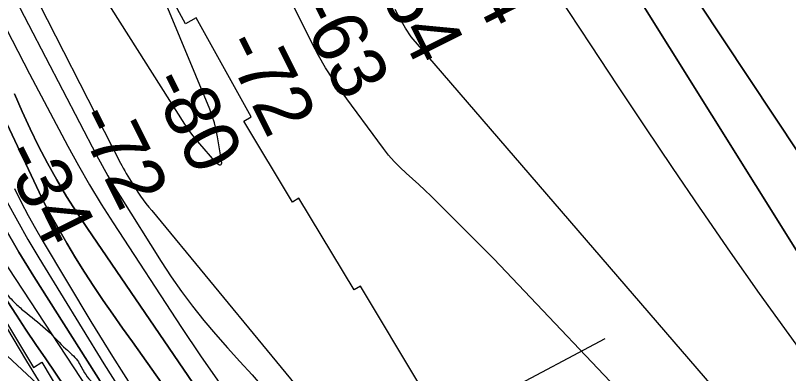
# Model space of a CAD drawing. Extents: x 3297753 to 3335611, y 652252 to 677623.
# Drawn here: x 3308869 to 3309808, y 671345 to 671780 of the extents above; entities that cross this region are included whole.
import ezdxf

# ---------------------------------------------------------------- set-up
doc = ezdxf.new("R2010")
doc.units = 0
for name, color, linetype in [('V-RIVR-EDGE', 7, 'Continuous'), ('V-RIVR-RANG', 7, 'Continuous'), ('V-RRAP-FSHR', 7, 'Continuous'), ('V-RRAP-RVMT', 7, 'Continuous'), ('V-TOPO-DPTH', 7, 'Continuous'), ('V-TOPO-MAJR', 7, 'Continuous'), ('V-TOPO-MINR', 7, 'Continuous'), ('V-TOPO-WATR', 7, 'Continuous')]:
    doc.layers.add(name, color=color, linetype=linetype)

msp = doc.modelspace()

# ---------------------------------------------------------------- linework, layer by layer
at = {"layer": 'V-RIVR-EDGE'}
msp.add_spline([(3307850.62, 675821), (3307850.75, 675819.26), (3307852.36, 675798.53), (3307852.34, 675791.07), (3307856.9, 675791.47), (3307860.2, 675784), (3307858.08, 675766.6), (3307858.03, 675745.87), (3307859.68, 675743.8), (3307863.41, 675742.96), (3307863.4, 675739.64), (3307862.94, 675720.99), (3307866.19, 675694.04), (3307864.47, 675668.35), (3307864.85, 675653.43), (3307866.04, 675632.29), (3307865.98, 675608.25), (3307860.93, 675578), (3307855.03, 675536.15), (3307852.01, 675490.98), (3307848.61, 675457.42), (3307845.62, 675420.95), (3307843.09, 675401.89), (3307841.81, 675387.8), (3307842.17, 675364.59), (3307841.69, 675337.23), (3307844.13, 675320.65), (3307845.74, 675299.92), (3307848.96, 675263.02), (3307851.37, 675230.27), (3307851.72, 675204.99), (3307854.14, 675179.28), (3307856.98, 675153.99), (3307856.53, 675138.24), (3307855.69, 675135.76), (3307856.07, 675118.35), (3307855.63, 675111.72), (3307854.35, 675095.97), (3307852.65, 675077.74), (3307852.18, 675054.11), (3307855.44, 675031.72), (3307862.38, 674991.5), (3307864.8, 674962.48), (3307868.44, 674926), (3307870.05, 674906.1), (3307872.46, 674875.01), (3307874.08, 674859.25), (3307876.52, 674843.5), (3307878.94, 674816.13), (3307882.53, 674757.68), (3307886.15, 674712.5), (3307885.71, 674704.21), (3307884.45, 674697.99), (3307884.44, 674691.78), (3307887.31, 674680.16), (3307887.28, 674668.97), (3307887.26, 674658.2), (3307885.58, 674651.15), (3307881.01, 674644.12), (3307881, 674639.97), (3307886.35, 674626.28), (3307890.03, 674605.55), (3307895.77, 674578.59), (3307899.43, 674550.81), (3307909.27, 674510.58), (3307914.59, 674481.97), (3307918.25, 674453.78), (3307918.22, 674440.51), (3307919.86, 674433.88), (3307927.3, 674423.08), (3307927.28, 674417.7), (3307927.25, 674404.02), (3307928.48, 674400.28), (3307931.78, 674393.23), (3307935.06, 674376.64), (3307944.54, 674357.55), (3307954.85, 674337.22), (3307963.92, 674316.06), (3307975.42, 674271.68), (3307986.49, 674225.23), (3308000.06, 674178.77), (3308007.44, 674148.91), (3308015.22, 674108.27), (3308020.53, 674078.42), (3308024.25, 674072.19), (3308025.04, 674059.34), (3308025.41, 674039.44), (3308027.79, 673997.16), (3308030.63, 673971.46), (3308027.69, 673955.3), (3308027.24, 673943.28), (3308027.64, 673935.82), (3308029.69, 673925.45), (3308035.46, 673911.76), (3308035.42, 673899.32), (3308034.12, 673873.21), (3308036.13, 673851.24), (3308038.54, 673818.91), (3308040.98, 673799), (3308046.76, 673788.21), (3308050.46, 673778.26), (3308048.79, 673772.46), (3308048.76, 673761.27), (3308053.68, 673740.53), (3308060.66, 673711.09), (3308069.7, 673678.73), (3308069.66, 673665.06), (3308067.15, 673653.46), (3308067.55, 673650.14), (3308072.94, 673649.3), (3308077.91, 673648.87), (3308079.98, 673646.38), (3308086.52, 673608.64), (3308091.84, 673582.1), (3308104.58, 673536.48), (3308114.83, 673495), (3308121.38, 673461), (3308123.83, 673446.07), (3308127.95, 673436.12), (3308140.31, 673406.24), (3308148.95, 673377.21), (3308153.04, 673357.72), (3308158.34, 673321.23), (3308169, 673273.12), (3308189.1, 673188.1), (3308196.88, 673150.37), (3308207.96, 673103.92), (3308212.04, 673079.45), (3308214.06, 673059.97), (3308216.51, 673045.04), (3308218.98, 673035.91), (3308226, 673025.53), (3308228.46, 673015.99), (3308228.43, 673002.32), (3308230.49, 672996.92), (3308235.04, 672992.77), (3308235.02, 672984.48), (3308237.47, 672972.87), (3308241.99, 672953.37), (3308247.32, 672933.05), (3308253.9, 672910.65), (3308257.61, 672901.53), (3308263.8, 672890.32), (3308276.17, 672865), (3308277.39, 672856.3), (3308278.62, 672850.08), (3308283.16, 672844.26), (3308286.05, 672839.7), (3308286.04, 672832.24), (3308285.59, 672818.97), (3308288.47, 672812.33), (3308293.83, 672800.3), (3308303.72, 672777.89), (3308309.9, 672762.54), (3308316.07, 672743.05), (3308316.44, 672725.64), (3308318.1, 672723.15), (3308323.06, 672717.33), (3308327.59, 672706.13), (3308331.69, 672690.37), (3308330.84, 672679.6), (3308330.4, 672672.14), (3308332.46, 672667.16), (3308337.42, 672658.44), (3308343.59, 672642.67), (3308347.7, 672625.26), (3308355.91, 672595.39), (3308355.89, 672584.62), (3308357.53, 672579.64), (3308362.07, 672570.92), (3308366.61, 672563.45), (3308376.07, 672534), (3308399.56, 672478.4), (3308411.51, 672452.67), (3308418.52, 672435.25), (3308421.79, 672418.66), (3308423.01, 672409.95), (3308425.49, 672403.73), (3308428.79, 672397.5), (3308430.01, 672387.55), (3308434.95, 672375.52), (3308444.41, 672344.83), (3308450.58, 672326.99), (3308456.78, 672320.76), (3308459.66, 672312.87), (3308465.4, 672287.99), (3308467.43, 672268.09), (3308473.18, 672249.01), (3308476.05, 672236.57), (3308485.95, 672214.16), (3308490.05, 672198.81), (3308495.86, 672201.7), (3308496.67, 672193), (3308499.08, 672161.9), (3308505.23, 672134.53), (3308513.87, 672107.57), (3308522.52, 672084.75), (3308527.9, 672082.25), (3308536.2, 672087.2), (3308540.76, 672086.78), (3308539.51, 672083.88), (3308535.76, 672077.67), (3308534.91, 672067.73), (3308534.47, 672059.44), (3308531.96, 672050.74), (3308533.2, 672047.42), (3308536.91, 672037.88), (3308550.93, 672008.42), (3308564.93, 671974.39), (3308569.87, 671959.46), (3308576.49, 671954.88), (3308585.14, 671932.48), (3308595.86, 671910.49), (3308604.94, 671895.13), (3308605.76, 671888.49), (3308607.82, 671885.17), (3308610.71, 671881.02), (3308616.47, 671862.77), (3308627.6, 671838.7), (3308640.39, 671816.29), (3308660.99, 671765.26), (3308672.95, 671740.77), (3308685.32, 671715.46), (3308698.53, 671692.21), (3308700.17, 671685.58), (3308711.29, 671658.19), (3308728.21, 671627.9), (3308743.07, 671602.99), (3308758.34, 671575.6), (3308771.97, 671554.84), (3308775.27, 671548.61), (3308783.11, 671536.16), (3308790.54, 671522.88), (3308793.43, 671519.55), (3308797.16, 671517.06), (3308801.29, 671511.24), (3308803.76, 671502.95), (3308810.8, 671502.1), (3308815.77, 671499.19), (3308833.53, 671474.28), (3308845.09, 671458.5), (3308857.08, 671443.55), (3308870.72, 671429.01), (3308882.71, 671418.61), (3308908.77, 671397), (3308930.27, 671375.39), (3308944.33, 671361.26), (3308952.58, 671346.74), (3308960.43, 671336.77), (3308966.22, 671331.78), (3308972.85, 671328.86), (3308985.64, 671307.28), (3309001.75, 671282.37), (3309010.84, 671271.57), (3309010.83, 671268.25), (3309008.34, 671266.19), (3309011.64, 671262.03), (3309018.66, 671250.83), (3309024.85, 671237.13), (3309035.15, 671212.24), (3309059.5, 671169.07), (3309066.5, 671150.82), (3309067.71, 671140.45), (3309071.85, 671135.88), (3309077.22, 671128.41), (3309078.45, 671123.02), (3309078.43, 671117.63), (3309082.15, 671111.4), (3309089.15, 671092.73), (3309098.63, 671073.23), (3309111.41, 671045.01), (3309116.36, 671032.15), (3309123.35, 671011), (3309128.7, 670995.65), (3309133.23, 670984.86), (3309143.97, 670967.42), (3309159.66, 670945.42), (3309169.17, 670933.37), (3309181.99, 670924.22), (3309188.19, 670917.16), (3309197.69, 670902.22), (3309217.1, 670874.81), (3309231.57, 670859.03), (3309239.82, 670845.33), (3309244.79, 670840.76), (3309252.23, 670835.35), (3309260.51, 670831.18), (3309275.4, 670817.06), (3309282.43, 670810.41), (3309290.69, 670800.02), (3309303.1, 670788.39), (3309315.92, 670775.51), (3309335.34, 670751), (3309344.42, 670736.47), (3309351.03, 670726.51), (3309360.13, 670721.51), (3309375.84, 670704.9), (3309390.72, 670688.69), (3309403.11, 670668.77), (3309415.49, 670646.77), (3309426.65, 670635.14), (3309442.78, 670618.52), (3309454.34, 670603.15), (3309462.18, 670588.63), (3309470.85, 670575.34), (3309476.63, 670563.31), (3309487.39, 670558.31), (3309488.62, 670554.57), (3309489.44, 670550.84), (3309494.82, 670544.2), (3309506.81, 670533.39), (3309523.77, 670518.84), (3309529.95, 670505.98), (3309538.6, 670484.82), (3309549.72, 670453.7), (3309551.35, 670440.85), (3309555.47, 670430.89), (3309568.67, 670408.89), (3309577.35, 670396.02), (3309581.47, 670386.48), (3309581.46, 670383.16), (3309578.55, 670379.85), (3309576.88, 670374.88), (3309582.24, 670364.09), (3309594.61, 670336.71), (3309604.49, 670308.91), (3309606.94, 670296.06), (3309614.38, 670284.85), (3309627.18, 670266.99), (3309635.46, 670261.59), (3309639.18, 670259.92), (3309638.74, 670249.97), (3309639.54, 670236.29), (3309641.18, 670228), (3309644.89, 670221.36), (3309656.46, 670208.06), (3309664.31, 670195.61), (3309663.46, 670188.15), (3309663.84, 670176.13), (3309667.96, 670166.17), (3309673.34, 670159.94), (3309684.07, 670142.92), (3309690.66, 670126.33), (3309700.14, 670102.68), (3309716.65, 670076.52)], degree=3, dxfattribs=at)
at = {"layer": 'V-RIVR-RANG'}
msp.add_line((3308312.46, 670714.58), (3309585.35, 671387.9), dxfattribs=at)
at = {"layer": 'V-RRAP-FSHR'}
msp.add_lwpolyline([(3309403.85, 670578.59), (3309349.68, 670652.53), (3309293.54, 670720.94), (3309232.98, 670779.2), (3309191.27, 670830.43), (3309151.05, 670877.63), (3309125.14, 670908.43), (3309099.86, 670957.89), (3309047.64, 671064.45), (3309009.56, 671150), (3308977.63, 671213.01), (3308944.15, 671273.53), (3308906.95, 671322.55), (3308835.2, 671388.92)], dxfattribs=at)
at = {"layer": 'V-RRAP-RVMT'}
for p, q in [((3309075.65, 671769.91), (3309007.16, 671895.15)), ((3309088.62, 671777.12), (3309075.65, 671769.91)), ((3309155.5, 671656.88), (3309088.62, 671777.12)), ((3309146.38, 671651.81), (3309155.5, 671656.88)), ((3309205.44, 671553.54), (3309146.38, 671651.81)), ((3309213.3, 671558.25), (3309205.44, 671553.54)), ((3309280.31, 671446.84), (3309213.3, 671558.25)), ((3308821.64, 671467.64), (3308890.83, 671352.85)), ((3309288.05, 671451.56), (3309280.31, 671446.84)), ((3309361.46, 671329.36), (3309288.05, 671451.56)), ((3308890.83, 671352.85), (3308901.22, 671359.12)), ((3308901.22, 671359.12), (3308968.27, 671247.65))]:
    msp.add_line(p, q, dxfattribs=at)
at = {"layer": 'V-TOPO-DPTH'}
for points in [[(3309107.24, 671248.55), (3309022.91, 671367.17), (3309011.03, 671383.91), (3308999.19, 671400.67), (3308987.39, 671417.45), (3308975.61, 671434.26), (3308964.08, 671451.22), (3308952.86, 671468.38), (3308942.09, 671485.83), (3308931.63, 671503.48), (3308912.07, 671537.51), (3308909.14, 671542.75), (3308906.29, 671548.04), (3308903.58, 671553.4), (3308900.95, 671558.8), (3308567.45, 672266.31)], [(3308567.45, 672266.31), (3308900.95, 671558.8), (3308903.58, 671553.4), (3308906.29, 671548.04), (3308909.14, 671542.75), (3308912.07, 671537.51), (3308931.63, 671503.48), (3308942.09, 671485.83), (3308952.86, 671468.38), (3308964.08, 671451.22), (3308975.61, 671434.26), (3308987.39, 671417.45), (3308999.19, 671400.67), (3309011.03, 671383.91), (3309022.91, 671367.17), (3309107.24, 671248.55)], [(3309610.04, 671826.88), (3309979.66, 671235.59), (3309993.7, 671213.35), (3310007.88, 671191.19), (3310022.25, 671169.17), (3310036.76, 671147.22), (3310065.13, 671104.72), (3310065.56, 671104.11), (3310066.95, 671102.33), (3310075.3, 671092.59), (3310078.96, 671088.41), (3310082.68, 671084.29), (3310086.48, 671080.25), (3310090.33, 671076.26), (3310094.24, 671072.31), (3310098.16, 671068.38), (3310102.09, 671064.46), (3310106.04, 671060.56), (3310458.09, 670714.16)], [(3310458.09, 670714.16), (3310106.04, 671060.56), (3310102.09, 671064.46), (3310098.16, 671068.38), (3310094.24, 671072.31), (3310090.33, 671076.26), (3310086.48, 671080.25), (3310082.68, 671084.29), (3310078.96, 671088.41), (3310075.3, 671092.59), (3310066.95, 671102.33), (3310065.56, 671104.11), (3310065.13, 671104.72), (3310036.76, 671147.22), (3310022.25, 671169.17), (3310007.88, 671191.19), (3309993.7, 671213.35), (3309979.66, 671235.59), (3309610.04, 671826.88)], [(3309698.7, 671796.28), (3309820.81, 671612.24), (3309873.03, 671533.93), (3309925.48, 671455.78), (3309978.3, 671377.86), (3310031.35, 671300.11), (3310127.28, 671160.19), (3310132.68, 671152.62), (3310138.25, 671145.19), (3310144.09, 671137.97), (3310150.11, 671130.88), (3310269.83, 670995.02), (3310288.28, 670974.89), (3310307.22, 670955.27), (3310326.91, 670936.4), (3310347.1, 670918.02), (3310367.83, 670900.24), (3310388.8, 670882.73)], [(3310388.8, 670882.73), (3310367.83, 670900.24), (3310347.1, 670918.02), (3310326.91, 670936.4), (3310307.22, 670955.27), (3310288.28, 670974.89), (3310269.83, 670995.02), (3310150.11, 671130.88), (3310144.09, 671137.97), (3310138.25, 671145.19), (3310132.68, 671152.62), (3310127.28, 671160.19), (3310031.35, 671300.11), (3309978.3, 671377.86), (3309925.48, 671455.78), (3309873.03, 671533.93), (3309820.81, 671612.24), (3309698.7, 671796.28)], [(3309090.35, 671325.23), (3308956.45, 671521.35), (3308943.6, 671540.8), (3308931.15, 671560.49), (3308919.31, 671580.56), (3308907.86, 671600.87), (3308897.07, 671621.52), (3308886.74, 671642.4), (3308877.09, 671663.61), (3308867.91, 671685.03)], [(3308867.91, 671685.03), (3308877.09, 671663.61), (3308886.74, 671642.4), (3308897.07, 671621.52), (3308907.86, 671600.87), (3308919.31, 671580.56), (3308931.15, 671560.49), (3308943.6, 671540.8), (3308956.45, 671521.35), (3309090.35, 671325.23)], [(3308867.94, 671569.98), (3308876.16, 671553.58), (3308884.66, 671537.32), (3308893.59, 671521.3), (3308902.8, 671505.43), (3308960.69, 671408.66), (3308986.84, 671366.15), (3309013.69, 671324.1)], [(3308867.94, 671569.98), (3308876.16, 671553.58), (3308884.66, 671537.32), (3308893.59, 671521.3), (3308902.8, 671505.43), (3308960.69, 671408.66), (3308986.84, 671366.15), (3309013.69, 671324.1)], [(3309799.18, 670274.45), (3309449.72, 670682.27), (3309431.61, 670703.69), (3309413.69, 670725.26), (3309396.06, 670747.06), (3309378.61, 670769.02), (3309348.33, 670807.63), (3309331.24, 670829.57), (3309314.25, 670851.57), (3309297.39, 670873.68), (3309280.63, 670895.86), (3309263.96, 670918.11), (3309247.33, 670940.39), (3309230.76, 670962.71), (3309214.22, 670985.06), (3309159.52, 671059.17), (3309116.32, 671119.05), (3309074, 671179.53), (3309033, 671240.91), (3308992.88, 671302.89), (3308891.59, 671463.15), (3308873.37, 671492.93), (3308855.74, 671523.04)], [(3309799.18, 670274.45), (3309449.72, 670682.27), (3309431.61, 670703.69), (3309413.69, 670725.26), (3309396.06, 670747.06), (3309378.61, 670769.02), (3309348.33, 670807.63), (3309331.24, 670829.57), (3309314.25, 670851.57), (3309297.39, 670873.68), (3309280.63, 670895.86), (3309263.96, 670918.11), (3309247.33, 670940.39), (3309230.76, 670962.71), (3309214.22, 670985.06), (3309159.52, 671059.17), (3309116.32, 671119.05), (3309074, 671179.53), (3309033, 671240.91), (3308992.88, 671302.89), (3308891.59, 671463.15), (3308873.37, 671492.93), (3308855.74, 671523.04)], [(3308859.18, 671433.52), (3308870.19, 671416.3), (3308881.45, 671399.22), (3308882.16, 671398.18), (3308893.96, 671380.7), (3308905.77, 671363.23), (3308917.59, 671345.77), (3308929.43, 671328.31)], [(3308929.43, 671328.31), (3308917.59, 671345.77), (3308905.77, 671363.23), (3308893.96, 671380.7), (3308882.16, 671398.18), (3308881.45, 671399.22), (3308870.19, 671416.3), (3308859.18, 671433.52)]]:
    msp.add_lwpolyline(points, dxfattribs=at)
at = {"layer": 'V-TOPO-MAJR'}
for points in [[(3310378.31, 670700.56), (3310305.01, 670780.44), (3310232.63, 670861.2), (3310059.72, 671057.6), (3310047.63, 671071.7), (3310035.77, 671086), (3310024.29, 671100.6), (3310013.06, 671115.39), (3309844.75, 671343.05), (3309808.53, 671392.63), (3309772.69, 671442.48), (3309737.42, 671492.73), (3309702.54, 671543.26), (3309700.52, 671546.21), (3309667.06, 671595.55), (3309633.78, 671645.01), (3309600.76, 671694.65), (3309567.92, 671744.41), (3309527.79, 671805.57)], [(3308850.96, 671777.56), (3308885.93, 671709.28), (3308932.55, 671621.48), (3308945.55, 671597.77), (3308958.99, 671574.3), (3308973.06, 671551.21), (3308987.55, 671528.38), (3309070.72, 671401.21), (3309093.76, 671367.08), (3309117.43, 671333.41)]]:
    msp.add_lwpolyline(points, dxfattribs=at)
at = {"layer": 'V-TOPO-MINR'}
for points in [[(3308567.45, 672266.31), (3308900.95, 671558.8), (3308903.58, 671553.4), (3308906.29, 671548.04), (3308909.14, 671542.75), (3308912.07, 671537.51), (3308931.63, 671503.48), (3308942.09, 671485.83), (3308952.86, 671468.38), (3308964.08, 671451.22), (3308975.61, 671434.26), (3308987.39, 671417.45), (3308999.19, 671400.67), (3309011.03, 671383.91), (3309022.91, 671367.17), (3309107.24, 671248.55)], [(3308758.83, 672065.66), (3308996.67, 671600.96), (3308998.35, 671597.77), (3309000.07, 671594.62), (3309001.87, 671591.5), (3309003.72, 671588.41), (3309017.79, 671565.46), (3309020.82, 671560.77), (3309023.99, 671556.18), (3309027.37, 671551.74), (3309030.89, 671547.4), (3309034.6, 671543.23), (3309594.92, 670863.72), (3309602.6, 670851.43), (3309610.68, 670839.43), (3309619.34, 670827.84), (3309628.41, 670816.54), (3309932.06, 670456.8)], [(3309827.11, 671044.64), (3309734.61, 671171.83), (3309716.14, 671196.28), (3309697.11, 671220.26), (3309677.23, 671243.54), (3309656.77, 671266.35), (3309635.9, 671288.82), (3309450.08, 671484.73), (3309373.72, 671560.73), (3309366.37, 671567.87), (3309358.93, 671574.91), (3309351.33, 671581.78), (3309343.62, 671588.54), (3309336.1, 671595.46), (3309328.92, 671602.69), (3309322.25, 671610.39), (3309315.92, 671618.41), (3309264.65, 671688.12), (3309254.83, 671702.22), (3309245.52, 671716.64), (3309236.96, 671731.51), (3309228.91, 671746.7), (3309112.9, 671979.98)], [(3308938.49, 671862.85), (3309074.37, 671648.27), (3309078.55, 671642), (3309082.91, 671635.86), (3309087.55, 671629.93), (3309092.38, 671624.14), (3309110.74, 671603.11), (3309113.49, 671600.59), (3309116.73, 671598.74), (3309117.92, 671598.7), (3309118.84, 671599.01), (3309119.36, 671599.83), (3309119.62, 671600.98), (3309114.44, 671632.75), (3309112.74, 671641.29), (3309110.66, 671649.73), (3309107.99, 671658), (3309104.93, 671666.16), (3309051.93, 671793.81)], [(3310458.09, 670714.16), (3310106.04, 671060.56), (3310102.09, 671064.46), (3310098.16, 671068.38), (3310094.24, 671072.31), (3310090.33, 671076.26), (3310086.48, 671080.25), (3310082.68, 671084.29), (3310078.96, 671088.41), (3310075.3, 671092.59), (3310066.95, 671102.33), (3310065.56, 671104.11), (3310065.13, 671104.72), (3310036.76, 671147.22), (3310022.25, 671169.17), (3310007.88, 671191.19), (3309993.7, 671213.35), (3309979.66, 671235.59), (3309610.04, 671826.88)], [(3308864.16, 671809.01), (3308967.52, 671610.42), (3308974.29, 671597.8), (3308981.26, 671585.31), (3308988.55, 671572.99), (3308996.04, 671560.79), (3309046.14, 671481.46), (3309058.27, 671463.02), (3309070.87, 671444.91), (3309084.14, 671427.29), (3309097.86, 671409.99), (3309112.11, 671393.12), (3309126.62, 671376.47), (3309141.51, 671360.15), (3309156.65, 671344.07), (3309515, 670925.27), (3309557.83, 670868.77), (3309573.84, 670848.05), (3309590.12, 670827.54), (3309606.79, 670807.35), (3309623.72, 670787.37), (3310064.1, 670277.7)], [(3310388.8, 670882.73), (3310367.83, 670900.24), (3310347.1, 670918.02), (3310326.91, 670936.4), (3310307.22, 670955.27), (3310288.28, 670974.89), (3310269.83, 670995.02), (3310150.11, 671130.88), (3310144.09, 671137.97), (3310138.25, 671145.19), (3310132.68, 671152.62), (3310127.28, 671160.19), (3310031.35, 671300.11), (3309978.3, 671377.86), (3309925.48, 671455.78), (3309873.03, 671533.93), (3309820.81, 671612.24), (3309698.7, 671796.28)], [(3310389.21, 670590.51), (3310352.03, 670627.69), (3310314.77, 670664.78), (3310277.38, 670701.76), (3310239.9, 670738.65), (3310202.78, 670775.86), (3310166.19, 670813.59), (3310130.42, 670852.08), (3310095.18, 670891.1), (3309976.3, 671025.58), (3309968.92, 671034.13), (3309961.67, 671042.79), (3309954.62, 671051.62), (3309947.71, 671060.56), (3309349.55, 671754.08), (3309342.6, 671764.81), (3309336.2, 671775.88), (3309330.16, 671787.17)], [(3308867.91, 671685.03), (3308877.09, 671663.61), (3308886.74, 671642.4), (3308897.07, 671621.52), (3308907.86, 671600.87), (3308919.31, 671580.56), (3308931.15, 671560.49), (3308943.6, 671540.8), (3308956.45, 671521.35), (3309090.35, 671325.23)], [(3308867.94, 671569.98), (3308876.16, 671553.58), (3308884.66, 671537.32), (3308893.59, 671521.3), (3308902.8, 671505.43), (3308960.69, 671408.66), (3308986.84, 671366.15), (3309013.69, 671324.1)], [(3308859.16, 671553.64), (3308871.38, 671530.76), (3308884.22, 671508.22), (3308897.48, 671485.92), (3308976.53, 671357.03), (3309009.82, 671304.18), (3309043.93, 671251.87), (3309079.27, 671200.38), (3309115.43, 671149.44), (3309140.19, 671115.43), (3309164.63, 671081.94), (3309189.13, 671048.5), (3309213.71, 671015.13), (3309238.36, 670981.79), (3309263.17, 670948.58), (3309288.14, 670915.5), (3309313.37, 670882.61), (3309338.76, 670849.85), (3309405.95, 670763.81), (3309417.65, 670749.03), (3309429.47, 670734.37), (3309441.49, 670719.86), (3309453.64, 670705.45), (3309656.3, 670468.38)], [(3308855.74, 671523.04), (3308873.37, 671492.93), (3308891.59, 671463.15), (3308992.88, 671302.89), (3309033, 671240.91), (3309074, 671179.53), (3309116.32, 671119.05), (3309159.52, 671059.17), (3309214.22, 670985.06), (3309230.76, 670962.71), (3309247.33, 670940.39), (3309263.96, 670918.11), (3309280.63, 670895.86), (3309297.39, 670873.68), (3309314.25, 670851.57), (3309331.24, 670829.57), (3309348.33, 670807.63), (3309378.61, 670769.02), (3309396.06, 670747.06), (3309413.69, 670725.26), (3309431.61, 670703.69), (3309449.72, 670682.27), (3309799.18, 670274.45)], [(3308851.7, 671486.88), (3309009.44, 671246.29), (3309056.23, 671176.37), (3309103.87, 671107.05), (3309152.79, 671038.63), (3309202.58, 670970.82), (3309285.17, 670860.47), (3309294.31, 670848.29), (3309303.48, 670836.12), (3309312.66, 670823.97), (3309321.87, 670811.84), (3309331.12, 670799.74), (3309340.41, 670787.67), (3309349.76, 670775.64), (3309359.14, 670763.64), (3309368.66, 670751.53), (3309382.95, 670733.6), (3309397.39, 670715.79), (3309412.05, 670698.16), (3309426.86, 670680.66), (3310105.48, 669889.22)], [(3308858.12, 671401.45), (3308882.55, 671360.3), (3308907.62, 671319.56), (3308933.68, 671279.43), (3308960.39, 671239.72), (3308987.61, 671200.34), (3309014.85, 671160.97), (3309042.13, 671121.62), (3309069.44, 671082.3), (3309093.7, 671047.4), (3309133.53, 670990.9), (3309173.84, 670934.77), (3309214.9, 670879.17), (3309256.44, 670823.92), (3309343.97, 670709.1), (3309350.47, 670700.69), (3309357.02, 670692.34), (3309363.68, 670684.06), (3309370.41, 670675.84), (3309536.56, 670475.2)]]:
    msp.add_lwpolyline(points, dxfattribs=at)
at = {"layer": 'V-TOPO-WATR'}
msp.add_lwpolyline([(3308859.18, 671433.52), (3308870.19, 671416.3), (3308881.45, 671399.22), (3308882.16, 671398.18), (3308893.96, 671380.7), (3308905.77, 671363.23), (3308917.59, 671345.77), (3308929.43, 671328.31)], dxfattribs=at)

# ---------------------------------------------------------------- texts
at = {"layer": 'V-RIVR-RANG'}
for s, p in [('-54', (3309388.41, 671876.89)), ('-54', (3309298.85, 671832.41)), ('-63', (3309208.69, 671789.12)), ('-72', (3309119.13, 671744.64)), ('-80', (3309030.16, 671698.98)), ('-72', (3308940, 671655.69)), ('-34', (3308850.32, 671611.45))]:
    msp.add_text(s, height=67, rotation=296.54997, dxfattribs=at).set_placement(p)

doc.saveas('drawing.dxf')
